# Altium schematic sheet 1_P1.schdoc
size 309 x 223 mm; Symbol: Sheet-Symbol_A4; Device: Sheet-Symbol_A4; @Page Name: P1; @Create Date: 2022-09-29; @Page Count: 1; @Page No: 1; @Project Name: BLDC; @Schematic Name: Schematic1; @Update Date: 2022-09-29; Company: 嘉立创EDA; Page Size: A4; Version: V1.0
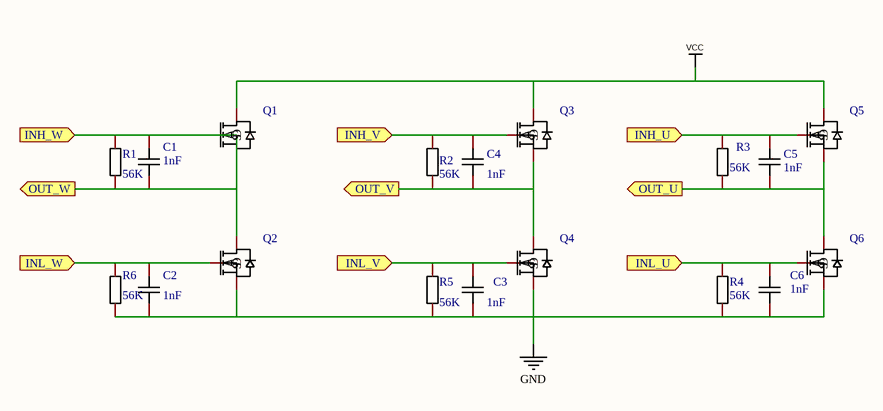
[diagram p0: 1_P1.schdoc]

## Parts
C1  value 1nF  [C0603]  (hidden comment: CAP_0603)
C2  value 1nF  [C0603]  (hidden comment: CAP_0603)
C3  value 1nF  [C0603]  (hidden comment: CAP_0603)
C4  value 1nF  [C0603]  (hidden comment: CAP_0603)
C5  value 1nF  [C0603]  (hidden comment: CAP_0603)
C6  value 1nF  [C0603]  (hidden comment: CAP_0603)
Q1  AO3400A_N  [SOT-23-3_L2.9-W1.3-P1.90-LS2.4-BR]  (value not drawn)
Q2  AO3400A_N  [SOT-23-3_L2.9-W1.3-P1.90-LS2.4-BR]  (value not drawn)
Q3  AO3400A_N  [SOT-23-3_L2.9-W1.3-P1.90-LS2.4-BR]  (value not drawn)
Q4  AO3400A_N  [SOT-23-3_L2.9-W1.3-P1.90-LS2.4-BR]  (value not drawn)
Q5  AO3400A_N  [SOT-23-3_L2.9-W1.3-P1.90-LS2.4-BR]  (value not drawn)
Q6  AO3400A_N  [SOT-23-3_L2.9-W1.3-P1.90-LS2.4-BR]  (value not drawn)
R1  value 56K  [R0603]  (hidden comment: Res_0603)
R2  value 56K  [R0603]  (hidden comment: Res_0603)
R3  value 56K  [R0603]  (hidden comment: Res_0603)
R4  value 56K  [R0603]  (hidden comment: Res_0603)
R5  value 56K  [R0603]  (hidden comment: Res_0603)
R6  value 56K  [R0603]  (hidden comment: Res_0603)

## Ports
INH_U (in), INH_V (in), INH_W (in), INL_U (in), INL_V (in), INL_W (in), OUT_U (out), OUT_V (out), OUT_W (out)

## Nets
GND: C2.1 C3.1 C6.1 Q2.2(S) Q4.2(S) Q6.2(S) R4.1 R5.1 R6.1
VCC: Q1.3(D) Q3.3(D) Q5.3(D)
INH_U: C5.2 Q5.1(G) R3.2 ; port INH_U
INH_V: C4.2 Q3.1(G) R2.2 ; port INH_V
INH_W: C1.1 C1.2 Q1.1(G) Q1.2(S) Q2.3(D) R1.1 R1.2 ; port INH_W, port OUT_W
INL_U: C6.2 Q6.1(G) R4.2 ; port INL_U
INL_V: C3.2 Q4.1(G) R5.2 ; port INL_V
INL_W: C2.2 Q2.1(G) R6.2 ; port INL_W
OUT_U: C5.1 Q5.2(S) Q6.3(D) R3.1 ; port OUT_U
OUT_V: C4.1 Q3.2(S) Q4.3(D) R2.1 ; port OUT_V

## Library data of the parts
C1-C6 = CAP_0603: Symbol: C1210X7R475K630NT; Convert to PCB: yes
Q1-Q6 = AO3400A_N: 类型:N沟道;漏源电压(Vdss):30V;连续漏极电流(Id):5.2A;功率(Pd):1W;导通电阻(RDS(on)@Vgs,Id):35mΩ@10V,5A;阈值电压(Vgs(th)@Id):1.5V@250A;; Symbol: N_MOS; Add into BOM: yes
R1-R6 = Res_0603: Symbol: 电阻; Convert to PCB: yes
